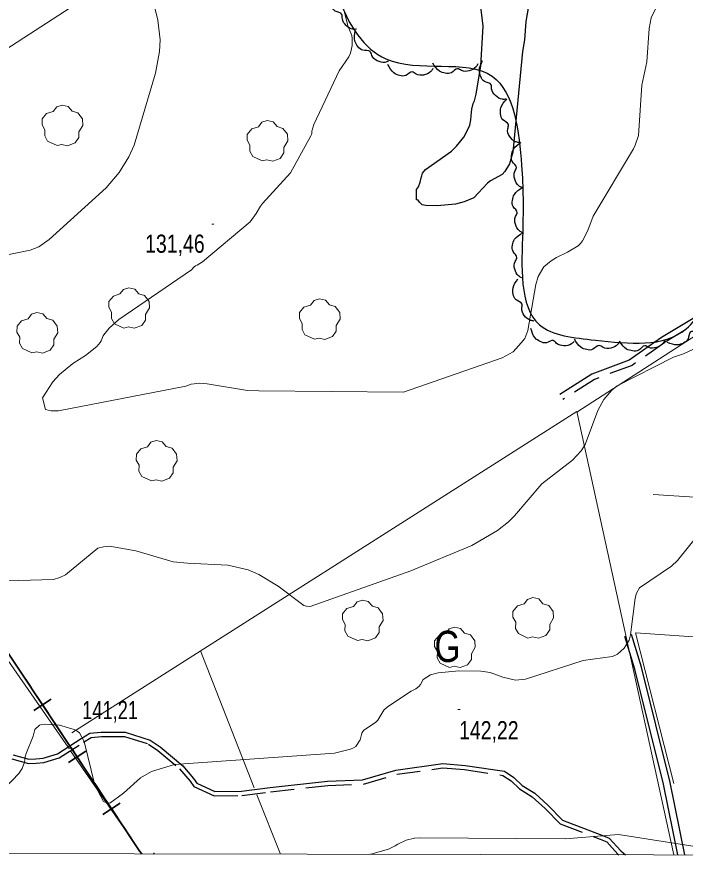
# Model space of a CAD drawing. Extents: x 483843 to 488449, y 4381269 to 4384483.
# Drawn here: x 486535.9 to 486857.1, y 4381816.7 to 4382221 of the extents above; entities that cross this region are included whole.
import ezdxf
from ezdxf.enums import TextEntityAlignment as Align

# ---------------------------------------------------------------- set-up
doc = ezdxf.new("R2010")
doc.units = 0
doc.header["$LTSCALE"] = 3.8
doc.linetypes.add('MEDIUM_DASHED', pattern=[4.5, 3, -1.5])
for name, color, linetype, lineweight in [('1', 7, 'Continuous', 13), ('27', 7, 'Continuous', 25), ('29', 7, 'Continuous', 13), ('34', 7, 'Continuous', 35), ('38', 7, 'Continuous', 25), ('51', 7, 'Continuous', 13), ('7', 7, 'Continuous', 13), ('8', 7, 'Continuous', 25), ('9', 7, 'Continuous', 13)]:
    doc.layers.add(name, color=color, linetype=linetype, lineweight=lineweight)
doc.layers.add('31', color=7, linetype='Continuous')

msp = doc.modelspace()

# ---------------------------------------------------------------- linework, layer by layer
at = {"layer": '1'}
msp.add_lwpolyline([(484100.5, 4384135.8), (487678, 4384129), (487674.1, 4381816.7), (484095.6, 4381823.6)], close=True, dxfattribs=at)
at = {"layer": '27'}
for points in [[(486286.37, 4382818.73), (486339.99, 4382829.8), (486391.37, 4382851.5), (486440.09, 4382863.84), (486483.65, 4382864.6), (486530.94, 4382876.91), (486556.13, 4382891.91), (486581.09, 4382903.76), (486654.31, 4382924.49), (486662.47, 4382925.04), (486711.17, 4382931.08), (486727.4, 4382937.04), (486766.91, 4382937.87), (486808.31, 4382909.18), (486821.81, 4382880.51), (486820.67, 4382841.64), (486812.49, 4382812.89), (486799.42, 4382770.69), (486791.78, 4382745.03), (486785, 4382714.29), (486784.58, 4382691.25), (486792.33, 4382675.66), (486812.73, 4382668.89), (486834.8, 4382649.92), (486842.09, 4382627.43), (486847.24, 4382607.13), (486841.07, 4382582.93), (486840.3, 4382544.36), (486820.33, 4382480.87), (486817.63, 4382459.06), (486815.97, 4382420.47), (486812.52, 4382387.85), (486799.99, 4382362.84), (486771.04, 4382337.85), (486733.51, 4382314.2), (486712.72, 4382296.59), (486687.38, 4382263.88), (486690.96, 4382229.15), (486713.22, 4382200.82), (486764.33, 4382192.43), (486778.5, 4382149.68), (486779.01, 4382117.89), (486787.15, 4382072.98), (486813.93, 4382065.66), (486857.54, 4382071.08), (486866.35, 4382080.34), (486893.23, 4382096.95), (486915.85, 4382116.25), (486928.06, 4382127.9), (486936.43, 4382157.7), (486928.1, 4382176.05), (486914.22, 4382205.24), (486902.98, 4382218.81), (486885.61, 4382249.79), (486879.29, 4382279.36), (486884.99, 4382315.26), (486888.52, 4382343.76), (486907.35, 4382375.88), (486922.54, 4382388.35), (486945.58, 4382366.33), (486954.28, 4382323.31), (486963.51, 4382283.6), (486982.52, 4382253.24), (487009.26, 4382225.98), (487037.6, 4382230.32), (487058.96, 4382252.37), (487069.68, 4382284.84), (487065.95, 4382338.17), (487054.24, 4382363.72), (487038.01, 4382386.56), (487027.59, 4382400.37), (487012.06, 4382422.24), (486991.9, 4382450.1), (486977.88, 4382471.56), (486976.21, 4382486.9), (486980.43, 4382521.64), (487024.88, 4382562.69), (487055.81, 4382565.06), (487106.74, 4382596.8), (487155.96, 4382614.11), (487207.74, 4382666.72), (487232.21, 4382676.6), (487267.31, 4382683.94), (487282.71, 4382693.48), (487294.56, 4382707.98), (487340.16, 4382736.84), (487389.67, 4382736.07), (487421.36, 4382716.33), (487454.29, 4382680.57), (487455.44, 4382629.06), (487501.37, 4382598.97)], [(486699.18, 4382215.04), (486697.41, 4382215.04), (486694.09, 4382216.88), (486692.33, 4382220.13), (486692.14, 4382222.17), (486688.95, 4382223.74), (486687.2, 4382226.15), (486686.6, 4382229.12), (486688.27, 4382233.79)], [(486714.51, 4382199.63), (486712.81, 4382199.12), (486709.1, 4382199.9), (486706.46, 4382202.48), (486705.68, 4382204.39), (486702.17, 4382204.94), (486699.79, 4382206.74), (486698.35, 4382209.4), (486698.56, 4382214.35)], [(486771.04, 4382181.42), (486769.26, 4382181.39), (486765.91, 4382183.17), (486764.08, 4382186.38), (486763.86, 4382188.42), (486760.64, 4382189.92), (486758.84, 4382192.3), (486758.18, 4382195.25), (486759.76, 4382199.96)], [(486735.85, 4382196.14), (486734.82, 4382194.7), (486731.4, 4382193.06), (486727.73, 4382193.5), (486725.96, 4382194.53), (486722.83, 4382192.83), (486719.85, 4382192.8), (486717.09, 4382194.03), (486714.24, 4382198.1)], [(486757.5, 4382198.46), (486756.58, 4382196.95), (486753.29, 4382195.05), (486749.6, 4382195.21), (486747.75, 4382196.1), (486744.77, 4382194.17), (486741.8, 4382193.91), (486738.95, 4382194.92), (486735.8, 4382198.75)], [(486777.18, 4382160.57), (486775.47, 4382161.02), (486772.72, 4382163.63), (486771.83, 4382167.22), (486772.16, 4382169.24), (486769.47, 4382171.56), (486768.38, 4382174.34), (486768.55, 4382177.36), (486771.33, 4382181.46)], [(486778.71, 4382138.94), (486777.16, 4382139.81), (486775.16, 4382143.04), (486775.2, 4382146.73), (486776.03, 4382148.6), (486774, 4382151.53), (486773.65, 4382154.49), (486774.57, 4382157.37), (486778.3, 4382160.64)], [(486779.02, 4382117.25), (486777.48, 4382118.13), (486775.5, 4382121.36), (486775.56, 4382125.05), (486776.41, 4382126.92), (486774.4, 4382129.86), (486774.06, 4382132.82), (486775, 4382135.7), (486778.75, 4382138.94)], [(486778.57, 4382095.55), (486777.05, 4382096.48), (486775.18, 4382099.78), (486775.36, 4382103.47), (486776.27, 4382105.31), (486774.36, 4382108.31), (486774.12, 4382111.28), (486775.15, 4382114.12), (486779.01, 4382117.25)], [(486784.51, 4382074.85), (486782.76, 4382075.14), (486779.78, 4382077.49), (486778.56, 4382080.97), (486778.71, 4382083.02), (486775.81, 4382085.08), (486774.47, 4382087.74), (486774.36, 4382090.76), (486776.75, 4382095.11)], [(486866.07, 4382077.32), (486866.25, 4382075.55), (486864.76, 4382072.06), (486861.72, 4382069.97), (486859.7, 4382069.58), (486858.48, 4382066.24), (486856.26, 4382064.25), (486853.37, 4382063.35), (486848.55, 4382064.52)], [(486803.8, 4382065.08), (486802.5, 4382063.87), (486798.82, 4382062.94), (486795.31, 4382064.09), (486793.78, 4382065.46), (486790.38, 4382064.41), (486787.45, 4382064.97), (486784.98, 4382066.72), (486782.99, 4382071.26)], [(486825.63, 4382065.1), (486824.66, 4382063.61), (486821.31, 4382061.83), (486817.63, 4382062.12), (486815.81, 4382063.08), (486812.76, 4382061.25), (486809.78, 4382061.09), (486806.97, 4382062.21), (486803.96, 4382066.15)], [(486847.32, 4382065.73), (486846.47, 4382064.17), (486843.27, 4382062.13), (486839.58, 4382062.13), (486837.69, 4382062.94), (486834.8, 4382060.87), (486831.84, 4382060.48), (486828.95, 4382061.37), (486825.63, 4382065.06)]]:
    msp.add_spline(points, degree=3, dxfattribs=at)
at = {"layer": '29'}
for points in [[(486555.22, 4382159.13), (486550.68, 4382161.25), (486549.27, 4382163.79), (486549.37, 4382166.77), (486548, 4382169.18), (486548.04, 4382171.93), (486550.2, 4382174.53), (486553.39, 4382175.53), (486555.04, 4382177.72), (486557.61, 4382178.55), (486560.47, 4382177.9), (486562.42, 4382175.63), (486565.23, 4382174.81), (486567.36, 4382171.96), (486567.6, 4382168.83), (486565.72, 4382165.68), (486565.72, 4382163), (486563.9, 4382160.39), (486560.28, 4382159.05), (486557.51, 4382159.68)], [(486653.78, 4382151.74), (486649.24, 4382153.86), (486647.83, 4382156.4), (486647.93, 4382159.38), (486646.56, 4382161.79), (486646.6, 4382164.54), (486648.76, 4382167.14), (486651.95, 4382168.14), (486653.6, 4382170.33), (486656.17, 4382171.16), (486659.03, 4382170.51), (486660.98, 4382168.24), (486663.79, 4382167.42), (486665.92, 4382164.57), (486666.16, 4382161.44), (486664.28, 4382158.29), (486664.28, 4382155.61), (486662.46, 4382153), (486658.84, 4382151.66), (486656.07, 4382152.29)], [(486587.28, 4382071.45), (486582.74, 4382073.57), (486581.33, 4382076.11), (486581.43, 4382079.09), (486580.06, 4382081.5), (486580.1, 4382084.25), (486582.26, 4382086.85), (486585.45, 4382087.85), (486587.1, 4382090.04), (486589.67, 4382090.87), (486592.53, 4382090.22), (486594.48, 4382087.95), (486597.29, 4382087.13), (486599.42, 4382084.28), (486599.66, 4382081.15), (486597.78, 4382078), (486597.78, 4382075.32), (486595.96, 4382072.71), (486592.34, 4382071.37), (486589.57, 4382072)], [(486678.9, 4382066.08), (486674.36, 4382068.2), (486672.95, 4382070.74), (486673.05, 4382073.72), (486671.68, 4382076.13), (486671.72, 4382078.88), (486673.88, 4382081.48), (486677.07, 4382082.48), (486678.72, 4382084.67), (486681.29, 4382085.5), (486684.15, 4382084.85), (486686.1, 4382082.58), (486688.91, 4382081.76), (486691.04, 4382078.91), (486691.28, 4382075.78), (486689.4, 4382072.63), (486689.4, 4382069.95), (486687.58, 4382067.34), (486683.96, 4382066), (486681.19, 4382066.63)], [(486543.13, 4382059.5), (486538.59, 4382061.62), (486537.18, 4382064.16), (486537.28, 4382067.14), (486535.91, 4382069.55), (486535.95, 4382072.3), (486538.11, 4382074.9), (486541.3, 4382075.9), (486542.95, 4382078.09), (486545.52, 4382078.92), (486548.38, 4382078.27), (486550.33, 4382076), (486553.14, 4382075.18), (486555.27, 4382072.33), (486555.51, 4382069.2), (486553.63, 4382066.05), (486553.63, 4382063.37), (486551.81, 4382060.76), (486548.19, 4382059.42), (486545.42, 4382060.05)], [(486600.52, 4381997.99), (486595.98, 4382000.11), (486594.57, 4382002.65), (486594.67, 4382005.63), (486593.3, 4382008.04), (486593.34, 4382010.79), (486595.5, 4382013.39), (486598.69, 4382014.39), (486600.34, 4382016.58), (486602.91, 4382017.41), (486605.77, 4382016.76), (486607.72, 4382014.49), (486610.53, 4382013.67), (486612.66, 4382010.82), (486612.9, 4382007.69), (486611.02, 4382004.54), (486611.02, 4382001.86), (486609.2, 4381999.25), (486605.58, 4381997.91), (486602.81, 4381998.54)], [(486781.5, 4381922.5), (486776.96, 4381924.62), (486775.55, 4381927.16), (486775.65, 4381930.14), (486774.28, 4381932.55), (486774.32, 4381935.3), (486776.48, 4381937.9), (486779.67, 4381938.9), (486781.32, 4381941.09), (486783.89, 4381941.92), (486786.75, 4381941.27), (486788.7, 4381939), (486791.51, 4381938.18), (486793.64, 4381935.33), (486793.88, 4381932.2), (486792, 4381929.05), (486792, 4381926.37), (486790.18, 4381923.76), (486786.56, 4381922.42), (486783.79, 4381923.05)], [(486699.55, 4381921.31), (486695.01, 4381923.43), (486693.6, 4381925.97), (486693.7, 4381928.95), (486692.33, 4381931.36), (486692.37, 4381934.11), (486694.53, 4381936.71), (486697.72, 4381937.71), (486699.37, 4381939.9), (486701.94, 4381940.73), (486704.8, 4381940.08), (486706.75, 4381937.81), (486709.56, 4381936.99), (486711.69, 4381934.14), (486711.93, 4381931.01), (486710.05, 4381927.86), (486710.05, 4381925.18), (486708.23, 4381922.57), (486704.61, 4381921.23), (486701.84, 4381921.86)], [(486743.85, 4381908.36), (486739.31, 4381910.48), (486737.9, 4381913.02), (486738, 4381916), (486736.63, 4381918.41), (486736.67, 4381921.16), (486738.83, 4381923.76), (486742.02, 4381924.76), (486743.67, 4381926.95), (486746.24, 4381927.78), (486749.1, 4381927.13), (486751.05, 4381924.86), (486753.86, 4381924.04), (486755.99, 4381921.19), (486756.23, 4381918.06), (486754.35, 4381914.91), (486754.35, 4381912.23), (486752.53, 4381909.62), (486748.91, 4381908.28), (486746.14, 4381908.91)]]:
    msp.add_lwpolyline(points, close=True, dxfattribs=at)
at = {"layer": '34'}
for p, q in [((486537.18, 4381907.04), (486542.71, 4381898.71)), ((486552.41, 4381893.16), (486544.08, 4381887.62)), ((486545.47, 4381894.55), (486551.01, 4381886.22)), ((486553.77, 4381882.06), (486559.31, 4381873.73)), ((486569, 4381868.18), (486560.67, 4381862.64)), ((486562.07, 4381869.57), (486567.6, 4381861.24)), ((486570.37, 4381857.08), (486575.9, 4381848.75)), ((486578.66, 4381844.59), (486584.2, 4381836.26)), ((486585.59, 4381843.19), (486577.27, 4381837.66)), ((486586.96, 4381832.1), (486592.5, 4381823.77)), ((486595, 4381820), (486595.97, 4381818.78)), ((486595, 4381820), (486595.97, 4381818.78)), ((486602.02, 4381819.19), (486601.49, 4381818.77))]:
    msp.add_line(p, q, dxfattribs=at)
msp.add_lwpolyline([(486265, 4382283), (486302, 4382227), (486409, 4382100), (486595, 4381820)], dxfattribs=at)
at = {"layer": '38'}
for points in [[(486870.52, 4382081.77), (486845.78, 4382066.93), (486830.25, 4382056.03), (486812.24, 4382049.35), (486796.85, 4382039.51)], [(486853.63, 4381818.28), (486846.66, 4381852.29), (486832.98, 4381907.58), (486828.08, 4381923.23)], [(486857.01, 4381818.28), (486849.89, 4381853.02), (486836.17, 4381908.47), (486831.24, 4381924.22)], [(486534.15, 4381866.38), (486541.68, 4381864.29), (486544.96, 4381864.43), (486548.48, 4381864.81), (486555.39, 4381866.82), (486566.85, 4381874.18), (486570.94, 4381876.75), (486576.43, 4381877.24), (486587.99, 4381877.33), (486600.01, 4381873.45), (486604.82, 4381870.17), (486615.59, 4381861.09), (486620.82, 4381854.96), (486622.37, 4381852.76), (486631.11, 4381848.76), (486643.92, 4381848.87), (486657.6, 4381850.66), (486685.22, 4381853.71), (486702.08, 4381854.36), (486718.03, 4381859.05), (486740.55, 4381862.22), (486751.3, 4381861.32), (486770.28, 4381858.49), (486774.71, 4381855.49), (486778.76, 4381851.68), (486784.84, 4381847.91), (486791.2, 4381842.1), (486798.16, 4381835.06), (486816.98, 4381827.8), (486820.62, 4381826.3), (486826.23, 4381820.19), (486828.44, 4381818.33)]]:
    msp.add_lwpolyline(points, dxfattribs=at)
at = {"layer": '38', "linetype": 'MEDIUM_DASHED'}
for points in [[(486871.98, 4382079.38), (486847.31, 4382064.58), (486831.56, 4382053.53), (486813.5, 4382046.82), (486798.36, 4382037.15)], [(486533.45, 4381864.43), (486541.44, 4381862.21), (486545.12, 4381862.37), (486548.88, 4381862.77), (486556.26, 4381864.92), (486567.96, 4381872.43), (486571.62, 4381874.73), (486576.53, 4381875.17), (486587.67, 4381875.26), (486599.09, 4381871.58), (486603.57, 4381868.52), (486614.13, 4381859.62), (486619.19, 4381853.7), (486620.99, 4381851.11), (486630.67, 4381846.69), (486644.06, 4381846.8), (486657.85, 4381848.61), (486685.38, 4381851.65), (486702.42, 4381852.3), (486718.46, 4381857.02), (486740.61, 4381860.14), (486751.06, 4381859.27), (486769.51, 4381856.51), (486773.42, 4381853.88), (486777.5, 4381850.03), (486783.59, 4381846.25), (486789.77, 4381840.61), (486797, 4381833.29), (486816.21, 4381825.89), (486819.41, 4381824.56), (486824.8, 4381818.7), (486825.23, 4381818.34)]]:
    msp.add_lwpolyline(points, dxfattribs=at)
at = {"layer": '51'}
for p, q in [((486624.09, 4381916.29), (486649.98, 4381850.54)), ((486561.72, 4381868.28), (486596.01, 4381818.78)), ((486662.53, 4381818.65), (486651.28, 4381847.23))]:
    msp.add_line(p, q, dxfattribs=at)
for points in [[(486720.46, 4382428.98), (486758.35, 4382352.97), (486392.69, 4382116.17)], [(486295.96, 4382244.9), (486365.15, 4382156.94), (486439.61, 4382046.67), (486483.97, 4381980.32), (486553.96, 4381879.48), (486560.46, 4381870.09)], [(486841.65, 4381991.54), (487013.57, 4381980.36), (486974.89, 4382140.58), (486805.05, 4382031.02)], [(486851.73, 4381818.29), (486804.97, 4382031.35), (486562.26, 4381876.95)], [(486851.68, 4381852.54), (486833.22, 4381924.99), (487233.16, 4381897.43)]]:
    msp.add_lwpolyline(points, dxfattribs=at)
at = {"layer": '7'}
for p, q in [((486629.63, 4382121.45), (486630.63, 4382121.45)), ((486747.91, 4381888.19), (486748.91, 4381888.19)), ((486560.49, 4381869.57), (486561.49, 4381869.57))]:
    msp.add_line(p, q, dxfattribs=at)
at = {"layer": '8'}
for points in [[(486785.83, 4382249.29), (486780.56, 4382218.76), (486779.86, 4382209.97), (486778.91, 4382204.33), (486774.28, 4382156.04), (486772.63, 4382150.31), (486770.48, 4382146.77), (486769.14, 4382145.33), (486763.59, 4382142.2), (486762.02, 4382141.02), (486755.5, 4382133.97), (486750.9, 4382132.11), (486746.77, 4382131), (486737.89, 4382130.17), (486732.53, 4382130.33), (486731.5, 4382130.49), (486730.67, 4382130.71), (486729.34, 4382131.94), (486728.73, 4382132.98), (486728.36, 4382133.08), (486727.9, 4382133.1), (486728.04, 4382137.97), (486728.96, 4382139.37), (486729.77, 4382141.51), (486730.14, 4382143.64), (486730.3, 4382144.17), (486730.47, 4382144.56), (486730.85, 4382145.91), (486732.31, 4382147.62), (486744.74, 4382156.45), (486747.23, 4382158.79), (486750.67, 4382163.22), (486752.88, 4382167.25), (486753.63, 4382169.03), (486754.14, 4382171.46), (486754.18, 4382173.41), (486754.55, 4382176.62), (486755.23, 4382179.4)], [(486755.23, 4382179.4), (486755.78, 4382180.62), (486756.62, 4382183.8), (486758.86, 4382197.43), (486760.06, 4382216.58), (486755.94, 4382250.2)]]:
    msp.add_lwpolyline(points, dxfattribs=at)
at = {"layer": '9'}
for points in [[(486836.2, 4382188.12), (486834.63, 4382164.06), (486833.08, 4382159.27), (486832.33, 4382157.62), (486812.81, 4382125.17), (486810.26, 4382118.33), (486807.77, 4382113.3), (486806.78, 4382112.13), (486805.66, 4382111.05), (486800.57, 4382107.96), (486795.21, 4382105.37), (486792.73, 4382103.82), (486789.16, 4382100.84), (486786.48, 4382096.21), (486785.28, 4382092.35), (486781.48, 4382070.32), (486779.98, 4382066.48), (486778.35, 4382064.31), (486774.37, 4382060.09), (486769.07, 4382057.12), (486721.77, 4382040.59), (486652.16, 4382041.23), (486646.74, 4382041.51), (486627.42, 4382044.69), (486623.77, 4382044.98), (486619.6, 4382044.45), (486617.05, 4382043.46), (486555.84, 4382031.61), (486552.31, 4382031.72), (486549.72, 4382032.27), (486548.14, 4382037.91), (486553.12, 4382045.61), (486556.31, 4382049.17), (486562.82, 4382054.36), (486568.83, 4382058.29), (486574.27, 4382062.61), (486575.87, 4382064.46), (486576.44, 4382065.28), (486577.42, 4382067.7), (486577.74, 4382068.22), (486580.22, 4382071.43), (486584.92, 4382075.56), (486619.78, 4382099.47), (486621.15, 4382100.86), (486621.76, 4382101.33), (486622.58, 4382101.64), (486625.1, 4382103.21), (486648.01, 4382122.45), (486650.98, 4382126.51), (486653.04, 4382130.09), (486653.91, 4382131.27), (486667.4, 4382146.08), (486677.13, 4382163.76), (486677.47, 4382164.48), (486677.58, 4382164.98), (486677.65, 4382166.08), (486678.63, 4382169.24), (486690.76, 4382195.05), (486695.51, 4382201.84), (486696.25, 4382203.58), (486696.99, 4382207.18), (486697.1, 4382210.56), (486696.93, 4382211.99), (486695.01, 4382216.74), (486689.82, 4382237.74)], [(486857.17, 4382236.59), (486855.91, 4382235.17), (486844.97, 4382227.43), (486843.04, 4382225.13), (486840.84, 4382220.51), (486839.74, 4382215.37), (486838.7, 4382199.4), (486836.2, 4382188.12)], [(486503.81, 4382101), (486542.32, 4382108.88), (486546.37, 4382110.43), (486551.47, 4382114.07), (486578.73, 4382138.91), (486585.06, 4382146.22), (486589.72, 4382153.7), (486592.3, 4382159.39), (486602.45, 4382193.98), (486604.49, 4382204.36), (486604.69, 4382210), (486603.68, 4382219.37), (486602.29, 4382224.72)], [(486860.8, 4382061.16), (486856.23, 4382059.05), (486851.55, 4382057.49), (486824.49, 4382043.76), (486821.82, 4382041.61), (486818.01, 4382037.14), (486815.1, 4382031.87), (486808.98, 4382015.52), (486807.14, 4382012.5), (486802.99, 4382008.03), (486788.22, 4381996.54), (486775.13, 4381981.28), (486772.16, 4381978.35), (486766.83, 4381974.17), (486754.61, 4381967.01), (486725.17, 4381954.82), (486676.86, 4381937.72), (486675.14, 4381937.77), (486674.42, 4381937.93), (486673.91, 4381938.14), (486673.8, 4381938.2), (486661.48, 4381947.45), (486652.24, 4381953.07), (486647, 4381955.25), (486637.3, 4381957.49), (486617.97, 4381958.48), (486610.93, 4381959.15), (486593.06, 4381964.35), (486580.43, 4381966.66), (486577.48, 4381966.35), (486574.78, 4381965.64), (486559.21, 4381952.8), (486556.47, 4381951.57), (486553.48, 4381950.61), (486514.59, 4381949.5)], [(486830.39, 4381922.2), (486830.81, 4381923.98), (486833.08, 4381941.62), (486833.76, 4381944.07), (486835.12, 4381946.57), (486850.47, 4381956.99), (486853.45, 4381959.7), (486863.98, 4381972.89)], [(486523.57, 4381843.59), (486536.8, 4381857.45), (486538.46, 4381859.84), (486539.62, 4381862.93), (486539.91, 4381865.44), (486540.36, 4381867.01), (486543.72, 4381875.31), (486544.55, 4381878.48), (486546.74, 4381880.71), (486547.9, 4381881.01), (486549.3, 4381881.18), (486556.35, 4381880.66), (486563.4, 4381878.61), (486564.81, 4381877.81), (486565.97, 4381876.91), (486568.17, 4381872.85), (486573.36, 4381851.78), (486577.55, 4381844.01), (486578.98, 4381843.28), (486580.53, 4381843.18), (486587.11, 4381847.93), (486595.34, 4381855.39), (486600.65, 4381858.4), (486611.61, 4381861.79), (486688.62, 4381867.24), (486696.2, 4381869.06), (486697.66, 4381869.72), (486698.85, 4381870.44), (486700.87, 4381873.6), (486701.7, 4381876.8), (486702.15, 4381877.55), (486702.69, 4381878.23), (486708.25, 4381881.95), (486708.86, 4381882.49), (486709.38, 4381883.04), (486712.28, 4381887.85), (486714.02, 4381889.49), (486725.36, 4381896.96), (486727.61, 4381898.16), (486729.03, 4381899.2), (486729.82, 4381900.15), (486731.23, 4381902.51), (486734.71, 4381904.86), (486738.42, 4381905.79), (486748.33, 4381906.79), (486758.86, 4381906.65), (486763.43, 4381905.98), (486769.43, 4381903.66), (486775.54, 4381902.21), (486780.28, 4381902.76), (486808.06, 4381911.68), (486822, 4381913.63), (486823.34, 4381914.1), (486824.56, 4381914.68), (486827.83, 4381917.64), (486830.11, 4381921.55), (486830.39, 4381922.2)], [(486876.23, 4381820.08), (486825.01, 4381828.04), (486799.48, 4381825.97), (486729.69, 4381826.49), (486726.94, 4381826.39), (486722.96, 4381825.42), (486718.99, 4381823.48), (486717.75, 4381822.58), (486714.51, 4381821.09), (486706.01, 4381818.57), (486706, 4381818.57), (486705.99, 4381818.57), (486705.98, 4381818.57), (486705.97, 4381818.57), (486705.96, 4381818.57), (486705.95, 4381818.57), (486705.94, 4381818.57), (486705.93, 4381818.57), (486705.92, 4381818.57), (486705.91, 4381818.57), (486705.9, 4381818.57), (486705.89, 4381818.57), (486705.88, 4381818.57), (486705.87, 4381818.57)], [(486705.87, 4381818.57), (486705.86, 4381818.57), (486705.85, 4381818.57), (486705.84, 4381818.57), (486705.83, 4381818.57)]]:
    msp.add_lwpolyline(points, dxfattribs=at)

# ---------------------------------------------------------------- texts
at = {"layer": '31', "width": 0.8}
msp.add_text('G', height=15, dxfattribs=at).set_placement((486742.86, 4381910.99), align=Align.CENTER)
at = {"layer": '7'}
for s, width, p in [('131,46', 0.8, (486597.52, 4382107.64)), ('141,21', 0.75, (486567.28, 4381883.52)), ('142,22', 0.8, (486748.41, 4381873.82))]:
    msp.add_text(s, height=8.75, dxfattribs=dict(at, width=width)).set_placement(p)

doc.saveas('drawing.dxf')
